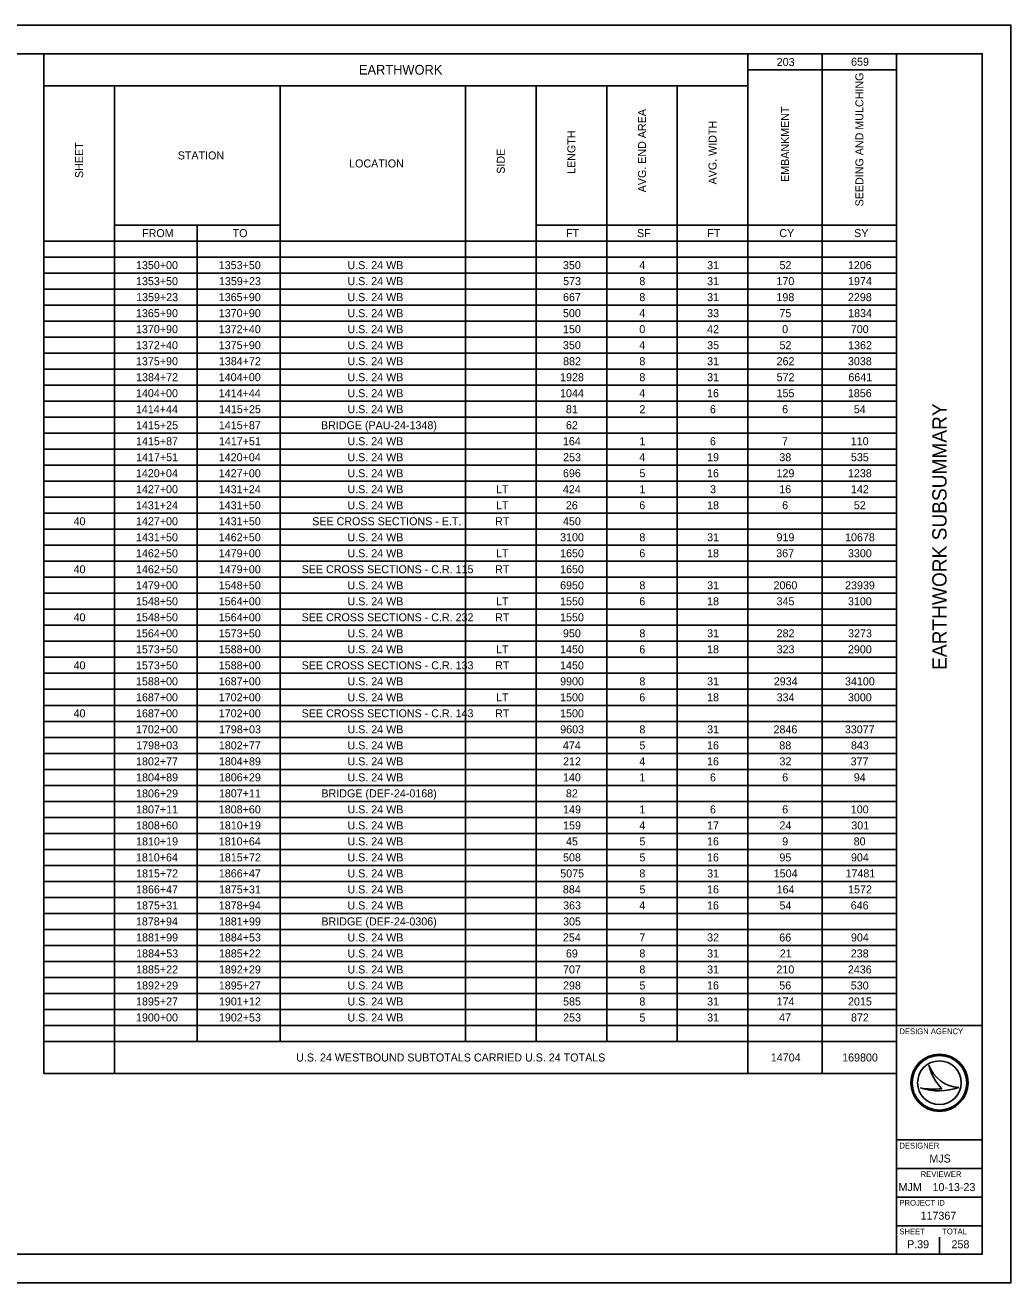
# Model space of a CAD drawing. Extents: x 0 to 34, y 0 to 22.
# Drawn here: x 16.75 to 34, y 0 to 22 of the extents above; entities that cross this region are included whole.
import ezdxf

# ---------------------------------------------------------------- set-up
doc = ezdxf.new("R2010")
doc.units = 0
for name, color, linetype in [('SH_Border', 7, 'Continuous'), ('SH_Cut_Line', 7, 'Continuous'), ('SH_Data', 7, 'Continuous'), ('SH_Text', 7, 'Continuous')]:
    doc.layers.add(name, color=color, linetype=linetype)

msp = doc.modelspace()

# ---------------------------------------------------------------- linework, layer by layer
at = {"layer": 'SH_Border'}
for p, q in [((32, 0.5), (32, 21.5)), ((32, 4.5), (33.5, 4.5)), ((32, 2.5), (33.5, 2.5)), ((32, 2), (33.5, 2)), ((32, 1.5), (33.5, 1.5)), ((32, 1), (33.5, 1))]:
    msp.add_line(p, q, dxfattribs=at)
msp.add_lwpolyline([(1.5, 21.5), (33.5, 21.5), (33.5, 0.5), (1.5, 0.5)], close=True, dxfattribs=at)
at = {"layer": 'SH_Cut_Line'}
msp.add_lwpolyline([(0, 0), (34, 0), (34, 22), (0, 22)], close=True, dxfattribs=at)
at = {"layer": 'SH_Data'}
for p, q in [((32.567, 3.81), (32.567, 3.81)), ((32.417, 3.41), (32.417, 3.41)), ((32.75, 3.5), (32.75, 3.5)), ((33.087, 3.419), (33.087, 3.419)), ((32.375, 0.675), (32.375, 0.675)), ((32.75, 0.5), (32.75, 0.8))]:
    msp.add_line(p, q, dxfattribs=at)
for radius in [0.5, 0.477, 0.477, 0.382]:
    msp.add_circle((32.75, 3.5), radius, dxfattribs=at)
for centre, radius, start, end in [((33.116, 3.998), 0.58, 198.9257, 198.9319), ((33.347, 3.97), 0.796, 191.6379, 191.6421), ((33.116, 3.998), 0.58, 198.9319, 267.1657), ((33.347, 3.97), 0.796, 191.6421, 226.0947), ((32.739, 4.37), 1.013, 251.4576, 290.0832), ((32.648, 4.654), 1.266, 259.4964, 259.4995), ((32.739, 4.37), 1.013, 251.4527, 251.4576), ((32.648, 4.654), 1.266, 259.4995, 276.6672)]:
    msp.add_arc(centre, radius, start, end, dxfattribs=at)
at = {"layer": 'SH_Text'}
for p, q in [((17.078, 21.5), (32, 21.5)), ((17.078, 21.5), (17.078, 3.662)), ((29.398, 21.5), (29.398, 3.662)), ((30.699, 21.5), (30.699, 3.662)), ((32, 21.5), (32, 3.662)), ((29.398, 21.22), (32, 21.22)), ((17.078, 20.94), (29.398, 20.94)), ((18.313, 20.94), (18.313, 3.662)), ((21.212, 20.94), (21.212, 18.222)), ((24.456, 20.94), (24.456, 4.222)), ((25.692, 20.94), (25.692, 4.222)), ((26.927, 20.94), (26.927, 4.222)), ((28.162, 20.94), (28.162, 4.222)), ((18.313, 18.502), (21.212, 18.502)), ((19.762, 18.502), (19.762, 4.222)), ((25.692, 18.502), (32, 18.502)), ((17.078, 18.222), (32, 18.222)), ((21.212, 18.222), (21.212, 4.222)), ((17.078, 17.942), (32, 17.942)), ((17.078, 17.662), (32, 17.662)), ((17.078, 17.382), (32, 17.382)), ((17.078, 17.102), (32, 17.102)), ((17.078, 16.822), (32, 16.822)), ((17.078, 16.542), (32, 16.542)), ((17.078, 16.262), (32, 16.262)), ((17.078, 15.982), (32, 15.982)), ((17.078, 15.702), (32, 15.702)), ((17.078, 15.422), (32, 15.422)), ((17.078, 15.142), (32, 15.142)), ((17.078, 14.862), (32, 14.862)), ((17.078, 14.582), (32, 14.582)), ((17.078, 14.302), (32, 14.302)), ((17.078, 14.022), (32, 14.022)), ((17.078, 13.742), (32, 13.742)), ((17.078, 13.462), (32, 13.462)), ((17.078, 13.182), (32, 13.182)), ((17.078, 12.902), (32, 12.902)), ((17.078, 12.622), (32, 12.622)), ((17.078, 12.342), (32, 12.342)), ((17.078, 12.062), (32, 12.062)), ((17.078, 11.782), (32, 11.782)), ((17.078, 11.502), (32, 11.502)), ((17.078, 11.222), (32, 11.222)), ((17.078, 10.942), (32, 10.942)), ((17.078, 10.662), (32, 10.662)), ((17.078, 10.382), (32, 10.382)), ((17.078, 10.102), (32, 10.102)), ((17.078, 9.822), (32, 9.822)), ((17.078, 9.542), (32, 9.542)), ((17.078, 9.262), (32, 9.262)), ((17.078, 8.982), (32, 8.982)), ((17.078, 8.702), (32, 8.702)), ((17.078, 8.422), (32, 8.422)), ((17.078, 8.142), (32, 8.142)), ((17.078, 7.862), (32, 7.862)), ((17.078, 7.582), (32, 7.582)), ((17.078, 7.302), (32, 7.302)), ((17.078, 7.022), (32, 7.022)), ((17.078, 6.742), (32, 6.742)), ((17.078, 6.462), (32, 6.462)), ((17.078, 6.182), (32, 6.182)), ((17.078, 5.902), (32, 5.902)), ((17.078, 5.622), (32, 5.622)), ((17.078, 5.342), (32, 5.342)), ((17.078, 5.062), (32, 5.062)), ((17.078, 4.782), (32, 4.782)), ((17.078, 4.502), (32, 4.502)), ((17.078, 4.222), (32, 4.222)), ((17.078, 3.662), (32, 3.662))]:
    msp.add_line(p, q, dxfattribs=at)

# ---------------------------------------------------------------- texts
at = {"layer": 'SH_Data'}
msp.add_text('EARTHWORK SUBSUMMARY', height=0.25, rotation=90, dxfattribs=at).set_placement((32.875, 10.722))
for s, height, p in [('DESIGN AGENCY', 0.1, (32.05, 4.35)), ('DESIGNER', 0.1, (32.05, 2.35)), ('MJS', 0.14, (32.574, 2.105)), ('REVIEWER', 0.1, (32.422, 1.85)), ('MJM', 0.14, (32.035, 1.605)), ('10-13-23', 0.14, (32.629, 1.605)), ('PROJECT ID', 0.1, (32.05, 1.35)), ('117367', 0.14, (32.42, 1.105)), ('SHEET', 0.1, (32.05, 0.85)), ('TOTAL', 0.1, (32.8, 0.85)), ('P.39', 0.14, (32.184, 0.605)), ('258', 0.14, (32.962, 0.605))]:
    msp.add_text(s, height=height, dxfattribs=at).set_placement(p)
at = {"layer": 'SH_Text'}
for s, height, p in [('203', 0.14, (29.903, 21.286)), ('659', 0.14, (31.204, 21.29)), ('EARTHWORK', 0.168, (22.591, 21.136)), ('STATION', 0.14, (19.421, 19.651)), ('LOCATION', 0.14, (22.42, 19.511)), ('FROM', 0.14, (18.797, 18.292)), ('TO', 0.14, (20.381, 18.292)), ('FT', 0.14, (26.216, 18.292)), ('SF', 0.14, (27.458, 18.292)), ('FT', 0.14, (28.687, 18.292)), ('CY', 0.14, (29.948, 18.292)), ('SY', 0.14, (31.258, 18.292)), ('1350+00', 0.14, (18.69, 17.732)), ('1353+50', 0.14, (20.139, 17.732)), ('U.S. 24 WB', 0.14, (22.391, 17.732)), ('350', 0.14, (26.162, 17.732)), ('4', 0.14, (27.497, 17.732)), ('31', 0.14, (28.685, 17.732)), ('52', 0.14, (29.951, 17.732)), ('1206', 0.14, (31.148, 17.732)), ('1353+50', 0.14, (18.69, 17.452)), ('1359+23', 0.14, (20.142, 17.452)), ('U.S. 24 WB', 0.14, (22.391, 17.452)), ('573', 0.14, (26.165, 17.452)), ('8', 0.14, (27.499, 17.452)), ('31', 0.14, (28.685, 17.452)), ('170', 0.14, (29.898, 17.452)), ('1974', 0.14, (31.152, 17.452)), ('1359+23', 0.14, (18.693, 17.172)), ('1365+90', 0.14, (20.139, 17.172)), ('U.S. 24 WB', 0.14, (22.391, 17.172)), ('667', 0.14, (26.163, 17.172)), ('8', 0.14, (27.499, 17.172)), ('31', 0.14, (28.685, 17.172)), ('198', 0.14, (29.898, 17.172)), ('2298', 0.14, (31.149, 17.172)), ('1365+90', 0.14, (18.69, 16.892)), ('1370+90', 0.14, (20.139, 16.892)), ('U.S. 24 WB', 0.14, (22.391, 16.892)), ('500', 0.14, (26.162, 16.892)), ('4', 0.14, (27.497, 16.892)), ('33', 0.14, (28.685, 16.892)), ('75', 0.14, (29.95, 16.892)), ('1834', 0.14, (31.152, 16.892)), ('1370+90', 0.14, (18.69, 16.612)), ('1372+40', 0.14, (20.139, 16.612)), ('U.S. 24 WB', 0.14, (22.391, 16.612)), ('150', 0.14, (26.162, 16.612)), ('0', 0.14, (27.498, 16.612)), ('42', 0.14, (28.685, 16.612)), ('0', 0.14, (29.998, 16.612)), ('700', 0.14, (31.199, 16.612)), ('1372+40', 0.14, (18.69, 16.332)), ('1375+90', 0.14, (20.139, 16.332)), ('U.S. 24 WB', 0.14, (22.391, 16.332)), ('350', 0.14, (26.162, 16.332)), ('4', 0.14, (27.497, 16.332)), ('35', 0.14, (28.685, 16.332)), ('52', 0.14, (29.951, 16.332)), ('1362', 0.14, (31.152, 16.332)), ('1375+90', 0.14, (18.69, 16.052)), ('1384+72', 0.14, (20.141, 16.052)), ('U.S. 24 WB', 0.14, (22.391, 16.052)), ('882', 0.14, (26.164, 16.052)), ('8', 0.14, (27.499, 16.052)), ('31', 0.14, (28.685, 16.052)), ('262', 0.14, (29.901, 16.052)), ('3038', 0.14, (31.149, 16.052)), ('1384+72', 0.14, (18.692, 15.772)), ('1404+00', 0.14, (20.139, 15.772)), ('U.S. 24 WB', 0.14, (22.391, 15.772)), ('1928', 0.14, (26.112, 15.772)), ('8', 0.14, (27.499, 15.772)), ('31', 0.14, (28.685, 15.772)), ('572', 0.14, (29.901, 15.772)), ('6641', 0.14, (31.157, 15.772)), ('1404+00', 0.14, (18.69, 15.492)), ('1414+44', 0.14, (20.139, 15.492)), ('U.S. 24 WB', 0.14, (22.391, 15.492)), ('1044', 0.14, (26.111, 15.492)), ('4', 0.14, (27.497, 15.492)), ('16', 0.14, (28.683, 15.492)), ('155', 0.14, (29.9, 15.492)), ('1856', 0.14, (31.148, 15.492)), ('1414+44', 0.14, (18.689, 15.212)), ('1415+25', 0.14, (20.142, 15.212)), ('U.S. 24 WB', 0.14, (22.391, 15.212)), ('81', 0.14, (26.214, 15.212)), ('2', 0.14, (27.5, 15.212)), ('6', 0.14, (28.734, 15.212)), ('6', 0.14, (29.998, 15.212)), ('54', 0.14, (31.252, 15.212)), ('1415+25', 0.14, (18.692, 14.932)), ('1415+87', 0.14, (20.14, 14.932)), ('BRIDGE (PAU-24-1348)', 0.14, (21.927, 14.932)), ('62', 0.14, (26.214, 14.932)), ('1415+87', 0.14, (18.691, 14.652)), ('1417+51', 0.14, (20.141, 14.652)), ('U.S. 24 WB', 0.14, (22.391, 14.652)), ('164', 0.14, (26.161, 14.652)), ('1', 0.14, (27.5, 14.652)), ('6', 0.14, (28.734, 14.652)), ('7', 0.14, (29.995, 14.652)), ('110', 0.14, (31.199, 14.652)), ('1417+51', 0.14, (18.692, 14.372)), ('1420+04', 0.14, (20.139, 14.372)), ('U.S. 24 WB', 0.14, (22.391, 14.372)), ('253', 0.14, (26.165, 14.372)), ('4', 0.14, (27.497, 14.372)), ('19', 0.14, (28.684, 14.372)), ('38', 0.14, (29.948, 14.372)), ('535', 0.14, (31.201, 14.372)), ('1420+04', 0.14, (18.689, 14.092)), ('1427+00', 0.14, (20.139, 14.092)), ('U.S. 24 WB', 0.14, (22.391, 14.092)), ('696', 0.14, (26.162, 14.092)), ('5', 0.14, (27.5, 14.092)), ('16', 0.14, (28.683, 14.092)), ('129', 0.14, (29.899, 14.092)), ('1238', 0.14, (31.149, 14.092)), ('1427+00', 0.14, (18.69, 13.812)), ('1431+24', 0.14, (20.139, 13.812)), ('U.S. 24 WB', 0.14, (22.391, 13.812)), ('LT', 0.14, (24.992, 13.812)), ('424', 0.14, (26.161, 13.812)), ('1', 0.14, (27.5, 13.812)), ('3', 0.14, (28.736, 13.812)), ('16', 0.14, (29.947, 13.812)), ('142', 0.14, (31.202, 13.812)), ('1431+24', 0.14, (18.689, 13.532)), ('1431+50', 0.14, (20.139, 13.532)), ('U.S. 24 WB', 0.14, (22.391, 13.532)), ('LT', 0.14, (24.992, 13.532)), ('26', 0.14, (26.213, 13.532)), ('6', 0.14, (27.498, 13.532)), ('18', 0.14, (28.684, 13.532)), ('6', 0.14, (29.998, 13.532)), ('52', 0.14, (31.252, 13.532)), ('40', 0.14, (17.598, 13.252)), ('1427+00', 0.14, (18.69, 13.252)), ('1431+50', 0.14, (20.139, 13.252)), ('SEE CROSS SECTIONS - E.T.', 0.14, (21.774, 13.252)), ('RT', 0.14, (24.974, 13.252)), ('450', 0.14, (26.162, 13.252)), ('1431+50', 0.14, (18.69, 12.972)), ('1462+50', 0.14, (20.139, 12.972)), ('U.S. 24 WB', 0.14, (22.391, 12.972)), ('3100', 0.14, (26.112, 12.972)), ('8', 0.14, (27.499, 12.972)), ('31', 0.14, (28.685, 12.972)), ('919', 0.14, (29.899, 12.972)), ('10678', 0.14, (31.099, 12.972)), ('1462+50', 0.14, (18.69, 12.692)), ('1479+00', 0.14, (20.139, 12.692)), ('U.S. 24 WB', 0.14, (22.391, 12.692)), ('LT', 0.14, (24.992, 12.692)), ('1650', 0.14, (26.112, 12.692)), ('6', 0.14, (27.498, 12.692)), ('18', 0.14, (28.684, 12.692)), ('367', 0.14, (29.894, 12.692)), ('3300', 0.14, (31.149, 12.692)), ('40', 0.14, (17.598, 12.412)), ('1462+50', 0.14, (18.69, 12.412)), ('1479+00', 0.14, (20.139, 12.412)), ('SEE CROSS SECTIONS - C.R. 115', 0.14, (21.589, 12.412)), ('RT', 0.14, (24.974, 12.412)), ('1650', 0.14, (26.112, 12.412)), ('1479+00', 0.14, (18.69, 12.132)), ('1548+50', 0.14, (20.139, 12.132)), ('U.S. 24 WB', 0.14, (22.391, 12.132)), ('6950', 0.14, (26.112, 12.132)), ('8', 0.14, (27.499, 12.132)), ('31', 0.14, (28.685, 12.132)), ('2060', 0.14, (29.847, 12.132)), ('23939', 0.14, (31.099, 12.132)), ('1548+50', 0.14, (18.69, 11.852)), ('1564+00', 0.14, (20.139, 11.852)), ('U.S. 24 WB', 0.14, (22.391, 11.852)), ('LT', 0.14, (24.992, 11.852)), ('1550', 0.14, (26.112, 11.852)), ('6', 0.14, (27.498, 11.852)), ('18', 0.14, (28.684, 11.852)), ('345', 0.14, (29.9, 11.852)), ('3100', 0.14, (31.149, 11.852)), ('40', 0.14, (17.598, 11.572)), ('1548+50', 0.14, (18.69, 11.572)), ('1564+00', 0.14, (20.139, 11.572)), ('SEE CROSS SECTIONS - C.R. 232', 0.14, (21.589, 11.572)), ('RT', 0.14, (24.974, 11.572)), ('1550', 0.14, (26.112, 11.572)), ('1564+00', 0.14, (18.69, 11.292)), ('1573+50', 0.14, (20.139, 11.292)), ('U.S. 24 WB', 0.14, (22.391, 11.292)), ('950', 0.14, (26.162, 11.292)), ('8', 0.14, (27.499, 11.292)), ('31', 0.14, (28.685, 11.292)), ('282', 0.14, (29.901, 11.292)), ('3273', 0.14, (31.152, 11.292)), ('1573+50', 0.14, (18.69, 11.012)), ('1588+00', 0.14, (20.139, 11.012)), ('U.S. 24 WB', 0.14, (22.391, 11.012)), ('LT', 0.14, (24.992, 11.012)), ('1450', 0.14, (26.112, 11.012)), ('6', 0.14, (27.498, 11.012)), ('18', 0.14, (28.684, 11.012)), ('323', 0.14, (29.901, 11.012)), ('2900', 0.14, (31.149, 11.012)), ('40', 0.14, (17.598, 10.732)), ('1573+50', 0.14, (18.69, 10.732)), ('1588+00', 0.14, (20.139, 10.732)), ('SEE CROSS SECTIONS - C.R. 133', 0.14, (21.589, 10.732)), ('RT', 0.14, (24.974, 10.732)), ('1450', 0.14, (26.112, 10.732)), ('1588+00', 0.14, (18.69, 10.452)), ('1687+00', 0.14, (20.139, 10.452)), ('U.S. 24 WB', 0.14, (22.391, 10.452)), ('9900', 0.14, (26.112, 10.452)), ('8', 0.14, (27.499, 10.452)), ('31', 0.14, (28.685, 10.452)), ('2934', 0.14, (29.851, 10.452)), ('34100', 0.14, (31.098, 10.452)), ('1687+00', 0.14, (18.69, 10.172)), ('1702+00', 0.14, (20.139, 10.172)), ('U.S. 24 WB', 0.14, (22.391, 10.172)), ('LT', 0.14, (24.992, 10.172)), ('1500', 0.14, (26.112, 10.172)), ('6', 0.14, (27.498, 10.172)), ('18', 0.14, (28.684, 10.172)), ('334', 0.14, (29.901, 10.172)), ('3000', 0.14, (31.149, 10.172)), ('40', 0.14, (17.598, 9.892)), ('1687+00', 0.14, (18.69, 9.892)), ('1702+00', 0.14, (20.139, 9.892)), ('SEE CROSS SECTIONS - C.R. 143', 0.14, (21.589, 9.892)), ('RT', 0.14, (24.974, 9.892)), ('1500', 0.14, (26.112, 9.892)), ('1702+00', 0.14, (18.69, 9.612)), ('1798+03', 0.14, (20.142, 9.612)), ('U.S. 24 WB', 0.14, (22.391, 9.612)), ('9603', 0.14, (26.114, 9.612)), ('8', 0.14, (27.499, 9.612)), ('31', 0.14, (28.685, 9.612)), ('2846', 0.14, (29.847, 9.612)), ('33077', 0.14, (31.095, 9.612)), ('1798+03', 0.14, (18.693, 9.332)), ('1802+77', 0.14, (20.14, 9.332)), ('U.S. 24 WB', 0.14, (22.391, 9.332)), ('474', 0.14, (26.161, 9.332)), ('5', 0.14, (27.5, 9.332)), ('16', 0.14, (28.683, 9.332)), ('88', 0.14, (29.948, 9.332)), ('843', 0.14, (31.202, 9.332)), ('1802+77', 0.14, (18.691, 9.052)), ('1804+89', 0.14, (20.141, 9.052)), ('U.S. 24 WB', 0.14, (22.391, 9.052)), ('212', 0.14, (26.164, 9.052)), ('4', 0.14, (27.497, 9.052)), ('16', 0.14, (28.683, 9.052)), ('32', 0.14, (29.951, 9.052)), ('377', 0.14, (31.196, 9.052)), ('1804+89', 0.14, (18.692, 8.772)), ('1806+29', 0.14, (20.141, 8.772)), ('U.S. 24 WB', 0.14, (22.391, 8.772)), ('140', 0.14, (26.162, 8.772)), ('1', 0.14, (27.5, 8.772)), ('6', 0.14, (28.734, 8.772)), ('6', 0.14, (29.998, 8.772)), ('94', 0.14, (31.252, 8.772)), ('1806+29', 0.14, (18.692, 8.492)), ('1807+11', 0.14, (20.141, 8.492)), ('BRIDGE (DEF-24-0168)', 0.14, (21.935, 8.492)), ('82', 0.14, (26.214, 8.492)), ('1807+11', 0.14, (18.692, 8.212)), ('1808+60', 0.14, (20.139, 8.212)), ('U.S. 24 WB', 0.14, (22.391, 8.212)), ('149', 0.14, (26.164, 8.212)), ('1', 0.14, (27.5, 8.212)), ('6', 0.14, (28.734, 8.212)), ('6', 0.14, (29.998, 8.212)), ('100', 0.14, (31.199, 8.212)), ('1808+60', 0.14, (18.69, 7.932)), ('1810+19', 0.14, (20.141, 7.932)), ('U.S. 24 WB', 0.14, (22.391, 7.932)), ('159', 0.14, (26.164, 7.932)), ('4', 0.14, (27.497, 7.932)), ('17', 0.14, (28.684, 7.932)), ('24', 0.14, (29.951, 7.932)), ('301', 0.14, (31.208, 7.932)), ('1810+19', 0.14, (18.692, 7.652)), ('1810+64', 0.14, (20.139, 7.652)), ('U.S. 24 WB', 0.14, (22.391, 7.652)), ('45', 0.14, (26.215, 7.652)), ('5', 0.14, (27.5, 7.652)), ('16', 0.14, (28.683, 7.652)), ('9', 0.14, (29.999, 7.652)), ('80', 0.14, (31.249, 7.652)), ('1810+64', 0.14, (18.689, 7.372)), ('1815+72', 0.14, (20.141, 7.372)), ('U.S. 24 WB', 0.14, (22.391, 7.372)), ('508', 0.14, (26.163, 7.372)), ('5', 0.14, (27.5, 7.372)), ('16', 0.14, (28.683, 7.372)), ('95', 0.14, (29.95, 7.372)), ('904', 0.14, (31.202, 7.372)), ('1815+72', 0.14, (18.692, 7.092)), ('1866+47', 0.14, (20.14, 7.092)), ('U.S. 24 WB', 0.14, (22.391, 7.092)), ('5075', 0.14, (26.114, 7.092)), ('8', 0.14, (27.499, 7.092)), ('31', 0.14, (28.685, 7.092)), ('1504', 0.14, (29.851, 7.092)), ('17481', 0.14, (31.107, 7.092)), ('1866+47', 0.14, (18.691, 6.812)), ('1875+31', 0.14, (20.141, 6.812)), ('U.S. 24 WB', 0.14, (22.391, 6.812)), ('884', 0.14, (26.161, 6.812)), ('5', 0.14, (27.5, 6.812)), ('16', 0.14, (28.683, 6.812)), ('164', 0.14, (29.901, 6.812)), ('1572', 0.14, (31.152, 6.812)), ('1875+31', 0.14, (18.692, 6.532)), ('1878+94', 0.14, (20.139, 6.532)), ('U.S. 24 WB', 0.14, (22.391, 6.532)), ('363', 0.14, (26.165, 6.532)), ('4', 0.14, (27.497, 6.532)), ('16', 0.14, (28.683, 6.532)), ('54', 0.14, (29.951, 6.532)), ('646', 0.14, (31.198, 6.532)), ('1878+94', 0.14, (18.689, 6.252)), ('1881+99', 0.14, (20.141, 6.252)), ('BRIDGE (DEF-24-0306)', 0.14, (21.935, 6.252)), ('305', 0.14, (26.164, 6.252)), ('1881+99', 0.14, (18.692, 5.972)), ('1884+53', 0.14, (20.142, 5.972)), ('U.S. 24 WB', 0.14, (22.391, 5.972)), ('254', 0.14, (26.161, 5.972)), ('7', 0.14, (27.499, 5.972)), ('32', 0.14, (28.685, 5.972)), ('66', 0.14, (29.947, 5.972)), ('904', 0.14, (31.202, 5.972)), ('1884+53', 0.14, (18.693, 5.692)), ('1885+22', 0.14, (20.141, 5.692)), ('U.S. 24 WB', 0.14, (22.391, 5.692)), ('69', 0.14, (26.214, 5.692)), ('8', 0.14, (27.499, 5.692)), ('31', 0.14, (28.685, 5.692)), ('21', 0.14, (29.957, 5.692)), ('238', 0.14, (31.199, 5.692)), ('1885+22', 0.14, (18.692, 5.412)), ('1892+29', 0.14, (20.141, 5.412)), ('U.S. 24 WB', 0.14, (22.391, 5.412)), ('707', 0.14, (26.163, 5.412)), ('8', 0.14, (27.499, 5.412)), ('31', 0.14, (28.685, 5.412)), ('210', 0.14, (29.898, 5.412)), ('2436', 0.14, (31.148, 5.412)), ('1892+29', 0.14, (18.692, 5.132)), ('1895+27', 0.14, (20.14, 5.132)), ('U.S. 24 WB', 0.14, (22.391, 5.132)), ('298', 0.14, (26.163, 5.132)), ('5', 0.14, (27.5, 5.132)), ('16', 0.14, (28.683, 5.132)), ('56', 0.14, (29.947, 5.132)), ('530', 0.14, (31.199, 5.132)), ('1895+27', 0.14, (18.691, 4.852)), ('1901+12', 0.14, (20.141, 4.852)), ('U.S. 24 WB', 0.14, (22.391, 4.852)), ('585', 0.14, (26.164, 4.852)), ('8', 0.14, (27.499, 4.852)), ('31', 0.14, (28.685, 4.852)), ('174', 0.14, (29.901, 4.852)), ('2015', 0.14, (31.15, 4.852)), ('1900+00', 0.14, (18.69, 4.572)), ('1902+53', 0.14, (20.142, 4.572)), ('U.S. 24 WB', 0.14, (22.391, 4.572)), ('253', 0.14, (26.165, 4.572)), ('5', 0.14, (27.5, 4.572)), ('31', 0.14, (28.685, 4.572)), ('47', 0.14, (29.945, 4.572)), ('872', 0.14, (31.202, 4.572)), ('U.S. 24 WESTBOUND SUBTOTALS CARRIED U.S. 24 TOTALS', 0.14, (21.493, 3.872)), ('14704', 0.14, (29.8, 3.872)), ('169800', 0.14, (31.048, 3.872))]:
    msp.add_text(s, height=height, dxfattribs=at).set_placement(p)
for s, p in [('SEEDING AND MULCHING', (31.419, 18.83)), ('AVG. END AREA', (27.615, 19.076)), ('EMBANKMENT', (30.118, 19.257)), ('AVG. WIDTH', (28.85, 19.214)), ('LENGTH', (26.379, 19.398)), ('SHEET', (17.765, 19.326)), ('SIDE', (25.144, 19.401))]:
    msp.add_text(s, height=0.14, rotation=90, dxfattribs=at).set_placement(p)

doc.saveas('drawing.dxf')
